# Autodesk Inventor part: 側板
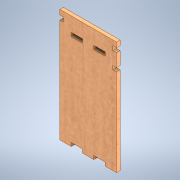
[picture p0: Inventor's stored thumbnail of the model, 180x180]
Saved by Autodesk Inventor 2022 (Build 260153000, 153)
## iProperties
Created: 2024-11
Part Number: 側板
Material: MDF 中密度繊維ボード
Document SubType Name: Modeling
Designer: shimizu
Density: 0.8 g/cm^3
Appearance: サクラ材 - ナチュラル 抑えた光沢
Author: shimizu
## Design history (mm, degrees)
sketch "スケッチ1"
  geometry: L1 (-20.243, 58.107)-(19.757, 58.107); L2 (-4.243, -21.893)-(-4.243, -19.393); L3 (-4.243, -19.393)-(-12.243, -19.393); L4 (-12.243, -19.393)-(-12.243, -21.893); L5 (11.757, -21.893)-(11.757, -19.393); L6 (11.757, -19.393)-(3.757, -19.393); L7 (3.757, -19.393)-(3.757, -21.893); L8 (-12.243, 48.107)-(-4.243, 48.107); L9 (-4.243, 48.107)-(-4.243, 45.607); L10 (-4.243, 45.607)-(-12.243, 45.607); L11 (-12.243, 45.607)-(-12.243, 48.107); L12 (3.757, 48.107)-(11.757, 48.107); L13 (11.757, 48.107)-(11.757, 45.607); L14 (11.757, 45.607)-(3.757, 45.607); L15 (3.757, 45.607)-(3.757, 48.107); L16 (-12.243, -21.893)-(-20.243, -21.893); L17 (19.757, -21.893)-(11.757, -21.893); L18 (3.757, -21.893)-(-4.243, -21.893); L19 (-20.243, 54.607)-(-17.743, 54.607); L20 (-17.743, 54.607)-(-17.743, 51.607); L21 (-17.743, 51.607)-(-20.243, 51.607); L22 (19.757, 54.607)-(17.257, 54.607); L23 (17.257, 54.607)-(17.257, 51.607); L24 (17.257, 51.607)-(19.757, 51.607); L25 (-20.243, -21.893)-(-20.243, 51.607); L26 (-20.243, 54.607)-(-20.243, 58.107); L27 (19.757, 58.107)-(19.757, 54.607); L28 (19.757, 51.607)-(19.757, -21.893); L29 (19.757, 42.427)-(17.257, 42.427); L30 (17.257, 42.427)-(17.257, 39.917); L31 (17.257, 39.917)-(19.757, 39.917); L32 (19.757, 39.917)-(19.757, 42.427); L33 (-20.243, -13.712)-(-17.743, -13.712); L34 (-17.743, -13.712)-(-17.743, -16.212); L35 (-17.743, -16.212)-(-20.243, -16.212); L36 (-20.243, -16.212)-(-20.243, -13.712); 3 further points
  constraints: 72 end point, 19 parallel, 8 perpendicular, 7 horizontal, 2 point on line
  dimensions: "d27" = 80 distance between parallel lines of L17 L1; "d28" = 40 distance between parallel lines of L25 L28; "d29" = 3.18 distance between parallel lines of L29 L14; "d30" = 2.5 distance of L30.end L31.end; "d31" = 2.5 distance between parallel lines of L16 L3; "d32" = 3.181 distance between parallel lines of L3 L35; "d33" = 2.5 distance of L33.end L34.end; "d34" = 2.5 distance between parallel lines of L36 L34; "d35" = 2.51 distance between parallel lines of L29 L31
extrude "押し出し1" new body sketch "スケッチ1" distance "d13" = 2.5; taper "d14" = 0 deg
node "ソリッド1"
